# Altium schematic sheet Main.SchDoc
size A; SheetNumber: 1; SheetTotal: 5
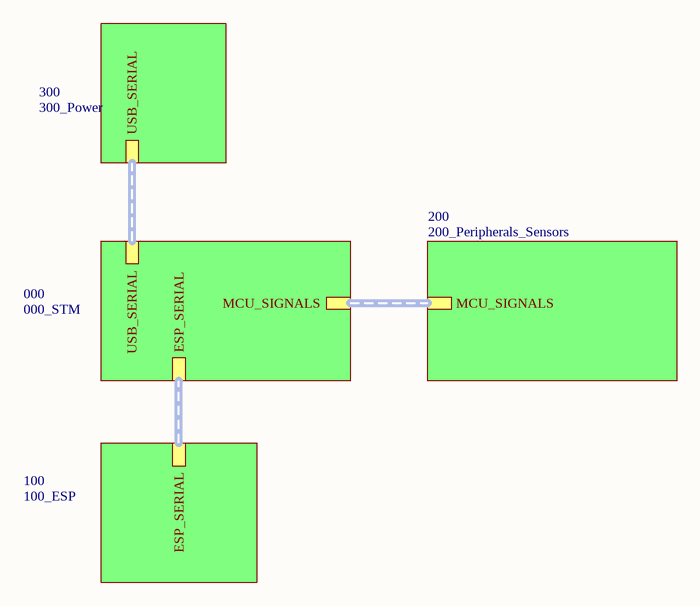
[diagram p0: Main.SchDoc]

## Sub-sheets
000 = 000_STM: MCU_SIGNALS (harness MCU_SIGNALS), USB_SERIAL (harness USB_SERIAL), ESP_SERIAL (harness ESP_SERIAL)
100 = 100_ESP: ESP_SERIAL (harness ESP_SERIAL)
200 = 200_Peripherals_Sensors: MCU_SIGNALS (harness MCU_SIGNALS)
300 = 300_Power: USB_SERIAL (harness USB_SERIAL)

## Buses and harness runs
harness sheet 000/ESP_SERIAL = sheet 100/ESP_SERIAL
harness sheet 000/MCU_SIGNALS = sheet 200/MCU_SIGNALS
harness sheet 000/USB_SERIAL = sheet 300/USB_SERIAL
